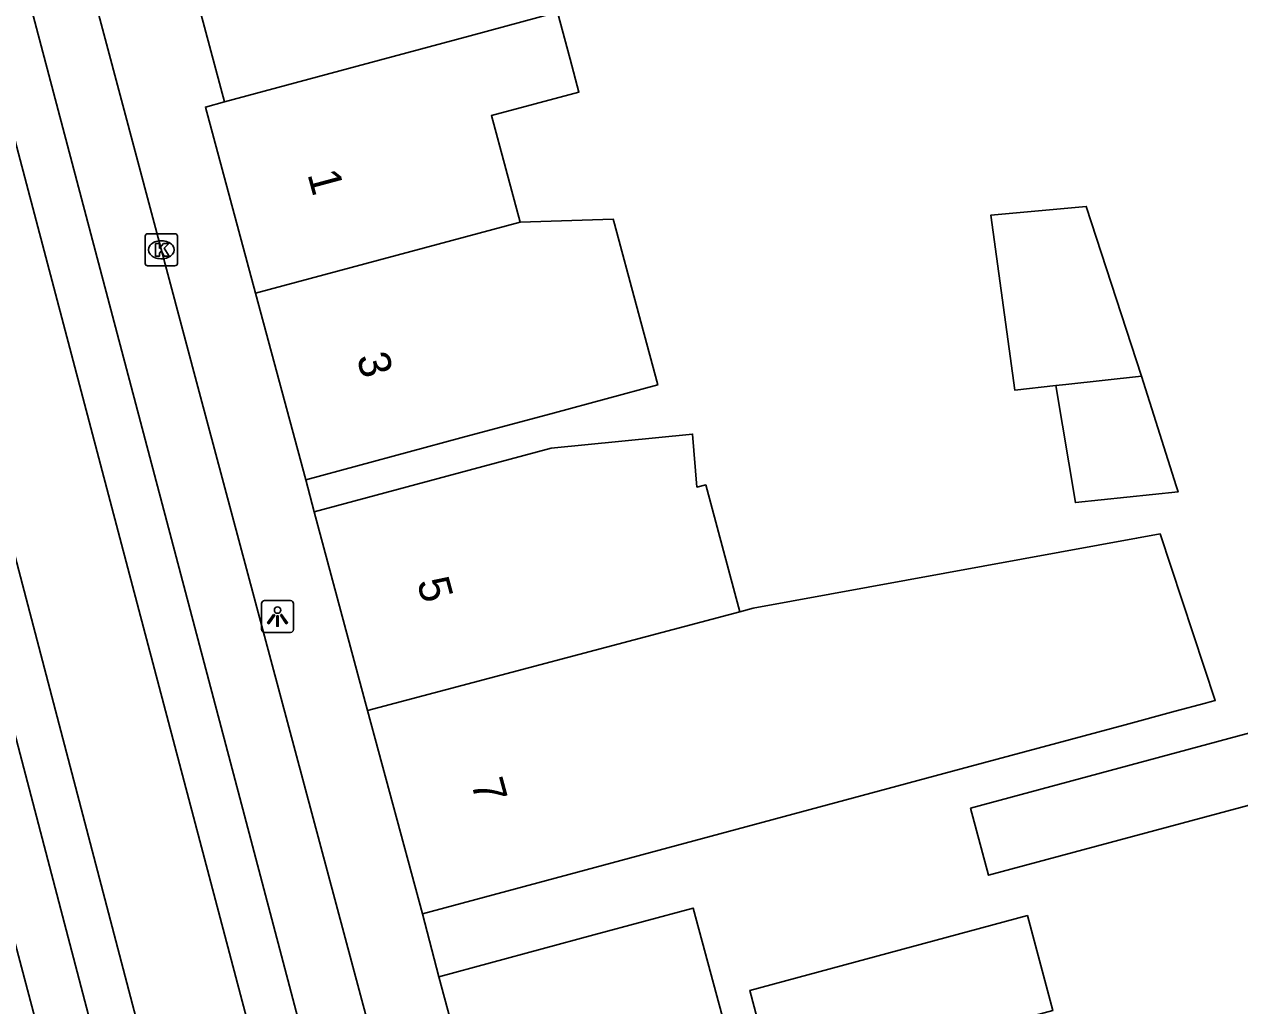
# Model space of a CAD drawing. Extents: x 159377 to 159983, y 382996 to 383595.
# Drawn here: x 159689.56 to 159727.42, y 383358.29 to 383388.85 of the extents above; entities that cross this region are included whole.
import ezdxf

# ---------------------------------------------------------------- set-up
doc = ezdxf.new("R2010")
doc.units = 0
for name, color, linetype in [('IMGEO_Kolk', 7, 'Continuous'), ('IMGEO_Lichtpunt', 7, 'Continuous'), ('IMGEO_Pand', 7, 'Continuous'), ('IMGEO_Pand_nummerreeks', 7, 'Continuous'), ('IMGEO_Rijbaan_lokaal_gesloten', 7, 'Continuous'), ('IMGEO_Voetpad_open', 7, 'Continuous')]:
    doc.layers.add(name, color=color, linetype=linetype)

msp = doc.modelspace()

# ---------------------------------------------------------------- linework, layer by layer
at = {"layer": 'IMGEO_Kolk'}
for p, q in [((159693.327, 383381.402), (159693.327, 383382.254)), ((159693.402, 383382.328), (159694.254, 383382.328)), ((159693.815, 383382.108), (159693.84, 383382.108)), ((159694.328, 383382.254), (159694.328, 383381.402)), ((159694.254, 383381.328), (159693.402, 383381.328)), ((159693.838, 383381.548), (159693.813, 383381.548))]:
    msp.add_line(p, q, dxfattribs=at)
for points in [[(159693.327, 383381.402), (159693.327, 383382.254)], [(159693.402, 383382.328), (159694.254, 383382.328)], [(159693.648, 383382.028), (159693.771, 383382.028), (159693.771, 383381.877), (159693.901, 383382.028), (159694.065, 383382.028), (159693.919, 383381.877), (159694.072, 383381.628), (159693.92, 383381.628), (159693.835, 383381.792), (159693.771, 383381.725), (159693.771, 383381.628), (159693.648, 383381.628), (159693.648, 383382.028)], [(159694.328, 383382.254), (159694.328, 383381.402)], [(159694.254, 383381.328), (159693.402, 383381.328)]]:
    msp.add_lwpolyline(points, dxfattribs=at)
for centre, start, end in [((159693.404, 383382.252), 91.552, 178.448), ((159693.404, 383382.252), 91.552, 178.448), ((159694.252, 383382.252), 1.552, 88.448), ((159694.252, 383382.252), 1.552, 88.448), ((159693.404, 383381.404), 181.552, 268.448), ((159693.404, 383381.404), 181.552, 268.448), ((159694.252, 383381.404), 271.552, 358.448), ((159694.252, 383381.404), 271.552, 358.448)]:
    msp.add_arc(centre, 0.0765, start, end, dxfattribs=at)
for centre, major_axis, ratio, start_param, end_param in [((159693.814, 383381.828), (-0.387, 0.002), 0.722429, 4.712389, 7.853982), ((159693.839, 383381.828), (-0.39, 0.002), 0.717154, 1.570796, 4.712389)]:
    msp.add_ellipse(centre, major_axis=major_axis, ratio=ratio, start_param=start_param, end_param=end_param, dxfattribs=at)
at = {"layer": 'IMGEO_Lichtpunt'}
for p, q in [((159696.95, 383370.809), (159696.95, 383370.002)), ((159696.95, 383370.809), (159696.95, 383370.002)), ((159697.852, 383370.904), (159697.044, 383370.904)), ((159697.852, 383370.904), (159697.044, 383370.904)), ((159697.946, 383370.002), (159697.946, 383370.809)), ((159697.946, 383370.002), (159697.946, 383370.809)), ((159697.044, 383369.908), (159697.852, 383369.908)), ((159697.044, 383369.908), (159697.852, 383369.908))]:
    msp.add_line(p, q, dxfattribs=at)
for points in [[(159697.324, 383370.473), (159697.363, 383370.445), (159697.175, 383370.183), (159697.137, 383370.21), (159697.324, 383370.473)], [(159697.426, 383370.425), (159697.473, 383370.425), (159697.473, 383370.103), (159697.426, 383370.103), (159697.426, 383370.425)], [(159697.536, 383370.445), (159697.574, 383370.472), (159697.761, 383370.21), (159697.722, 383370.182), (159697.536, 383370.445)]]:
    msp.add_lwpolyline(points, dxfattribs=at)
msp.add_circle((159697.449, 383370.607), 0.0994, dxfattribs=at)
for centre, start, end in [((159697.044, 383370.809), 90, 180), ((159697.044, 383370.809), 90, 180), ((159697.852, 383370.809), 0, 90), ((159697.852, 383370.809), 0, 90), ((159697.044, 383370.002), 180, 270), ((159697.044, 383370.002), 180, 270), ((159697.852, 383370.002), 270, 0), ((159697.852, 383370.002), 270, 360)]:
    msp.add_arc(centre, 0.0946, start, end, dxfattribs=at)
at = {"layer": 'IMGEO_Pand'}
for points in [[(159695.793, 383386.432), (159700.622, 383387.732), (159703.447, 383388.493), (159706.168, 383389.226), (159706.561, 383387.767), (159706.838, 383386.738), (159704.111, 383386.004), (159705.003, 383382.691)], [(159696.764, 383380.472), (159695.202, 383386.273), (159695.793, 383386.432)], [(159724.367, 383377.893), (159722.641, 383383.18), (159719.665, 383382.902), (159720.418, 383377.454), (159721.695, 383377.596)], [(159705.003, 383382.691), (159707.903, 383382.782), (159707.943, 383382.633), (159708.62, 383380.119), (159709.293, 383377.62), (159706.075, 383376.754), (159703.155, 383375.968), (159698.326, 383374.668)], [(159705.003, 383382.691), (159696.764, 383380.472)], [(159698.326, 383374.668), (159696.764, 383380.472)], [(159721.695, 383377.596), (159722.009, 383377.631), (159724.367, 383377.893)], [(159721.695, 383377.596), (159722.306, 383373.955), (159725.503, 383374.287), (159725.442, 383374.481), (159724.367, 383377.893)], [(159698.591, 383373.663), (159703.42, 383374.963), (159705.971, 383375.65), (159710.377, 383376.086), (159710.513, 383374.438), (159710.788, 383374.507), (159711.852, 383370.554)], [(159700.256, 383367.478), (159698.591, 383373.663)], [(159711.852, 383370.554), (159712.266, 383370.665), (159724.21, 383372.844), (159724.943, 383372.978), (159726.661, 383367.793), (159726.507, 383367.751), (159726.361, 383367.712), (159725.412, 383367.457), (159723.85, 383367.036), (159719.014, 383365.734), (159706.791, 383362.443), (159701.962, 383361.143)], [(159711.852, 383370.554), (159700.256, 383367.478)], [(159701.962, 383361.143), (159700.256, 383367.478)], [(159719.034, 383364.443), (159719.598, 383362.35), (159728.566, 383364.765), (159728.003, 383366.858), (159719.034, 383364.443)], [(159702.478, 383359.191), (159707.306, 383360.492), (159710.4, 383361.325), (159711.489, 383357.283), (159712.485, 383357.551), (159712.159, 383358.763), (159720.808, 383361.092), (159721.603, 383358.136), (159717.318, 383356.983)], [(159704.034, 383353.41), (159702.478, 383359.191)]]:
    msp.add_lwpolyline(points, dxfattribs=at)
at = {"layer": 'IMGEO_Rijbaan_lokaal_gesloten'}
for points in [[(159706.907, 383324.871), (159703.844, 383336.06), (159696.414, 383364.212), (159689.359, 383390.944), (159681.054, 383422.407), (159675.902, 383441.929), (159673.093, 383452.571), (159671.587, 383458.28)], [(159670.094, 383457.885), (159670.625, 383455.872), (159678.409, 383426.38), (159686.465, 383395.857), (159692.786, 383371.909), (159698.534, 383350.133), (159705.315, 383324.44), (159706.001, 383324.626), (159706.907, 383324.871)], [(159700.731, 383323.191), (159702.049, 383323.57), (159696.447, 383345.036), (159693.274, 383357.013), (159667.185, 383456.552), (159667.027, 383457.076)], [(159700.731, 383323.191), (159691.898, 383356.687), (159665.691, 383456.728)]]:
    msp.add_lwpolyline(points, dxfattribs=at)
at = {"layer": 'IMGEO_Voetpad_open'}
for points in [[(159695.793, 383386.432), (159689.89, 383408.493), (159681.184, 383441.029), (159670.697, 383478.285), (159669.551, 383482.179), (159664.244, 383500), (159658.841, 383518.144)], [(159663.864, 383456.282), (159664.964, 383452.218), (159665.106, 383451.555), (159670.1, 383433.187), (159678.787, 383399.561), (159682.877, 383384.322), (159688.475, 383363.216), (159690.31, 383356.311), (159696.363, 383333.532), (159698.5, 383325.536), (159698.524, 383325.331)], [(159690.128, 383395.731), (159695.004, 383377.404), (159700.034, 383358.613), (159702.961, 383347.681), (159705.825, 383336.598), (159706.48, 383334.224)], [(159698.591, 383373.663), (159698.326, 383374.668)], [(159702.478, 383359.191), (159701.962, 383361.143)]]:
    msp.add_lwpolyline(points, dxfattribs=at)

# ---------------------------------------------------------------- texts
at = {"layer": 'IMGEO_Pand_nummerreeks'}
for s, rotation, p in [('1', 285.0686, (159698.375, 383384.184)), ('3', 285.0628, (159699.907, 383378.491)), ('5', 285.0686, (159701.786, 383371.491)), ('7', 285.0743, (159703.471, 383365.232))]:
    msp.add_text(s, height=1, rotation=rotation, dxfattribs=at).set_placement(p)

doc.saveas('drawing.dxf')
